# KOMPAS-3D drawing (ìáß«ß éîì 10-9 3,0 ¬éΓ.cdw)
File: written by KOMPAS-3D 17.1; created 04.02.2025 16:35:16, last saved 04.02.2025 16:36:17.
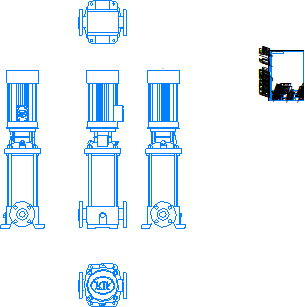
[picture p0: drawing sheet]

Sheet 1: A4, portrait

Title block, sheet 1: name: Насос ВМН 10-9 3,0 / кВт; designation: Насос ВМН 10-9 3,0 кВт; material: Сталь 10  ГОСТ 1050-2013; mass: 64,04; sheets: 1; sheet format: A4; stored path: \\adlc.lan\data\АДЛ_ПКД\3D-модели\ADL production\Насосы ГРАНПАМП\Насосы ВМН\ВМН10\KOMPAS 3D\Насос ВМН 10-9 3,0 кВт.cdw

Views: Вид 1, Спереди, Проекционный вид 2, Проекционный вид 3, Проекционный вид 4, Проекционный вид 5
Referenced files in \\adlc.lan\data\АДЛ_ПКД\3D-модели\ADL production\Насосы ГРАНПАМП\Насосы ВМН\ВМН10\KOMPAS 3D\: ВМН 10-9 3,0 кВт.m3d, Насос ВМН 10-9 3,0 кВт.m3d
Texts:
  Andrey
  АДЛ
Dimensions and other numbers on the sheet: 1:1; 1; 64,04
